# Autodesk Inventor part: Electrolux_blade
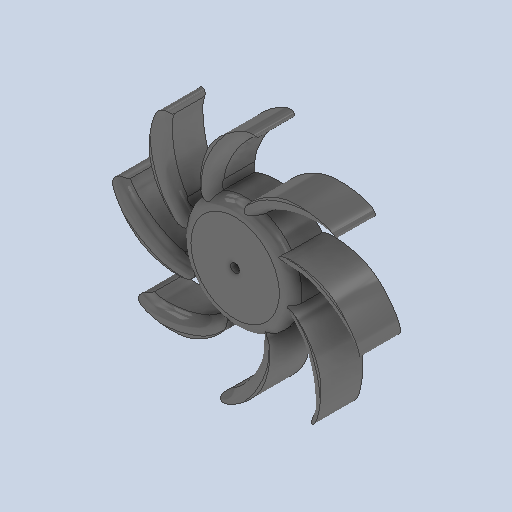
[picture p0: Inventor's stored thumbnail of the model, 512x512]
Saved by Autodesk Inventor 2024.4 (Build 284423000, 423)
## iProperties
Created: 2025-05
Part Number: Electrolux_blade
Material: Generic
Description: Electrolux_blade
Document SubType Name: Modeling
Designer: AdminForWorker
Density: 1 g/cm^3
Appearance: Default
Title: Electrolux_blade v4
Author: AdminForWorker
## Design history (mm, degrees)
feature "Body1"
body "Solid1"
